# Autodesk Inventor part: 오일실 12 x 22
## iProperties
IsCustomPart: 0
Created: 2009-02
Part Number: 오일실 12 x 22
Material: 고무
Description: 오일-실
Document SubType Name: Modeling
Standard: KS B 2804
Designer: SeoGD™
Standards Organization: KS
Language: ko-KR
Size Designation: S - 12 22 7
Categories: <MemberInstance><Categories><Category DisplayName="샤프트 부품" InternalName="7f7aeb1f-a693-4053-b835-cee3144e0d98" Mnemonic="SHFT"><Category DisplayName="실링" Intern
Density: 0.93 g/cm^3
Author: SeoGD™
